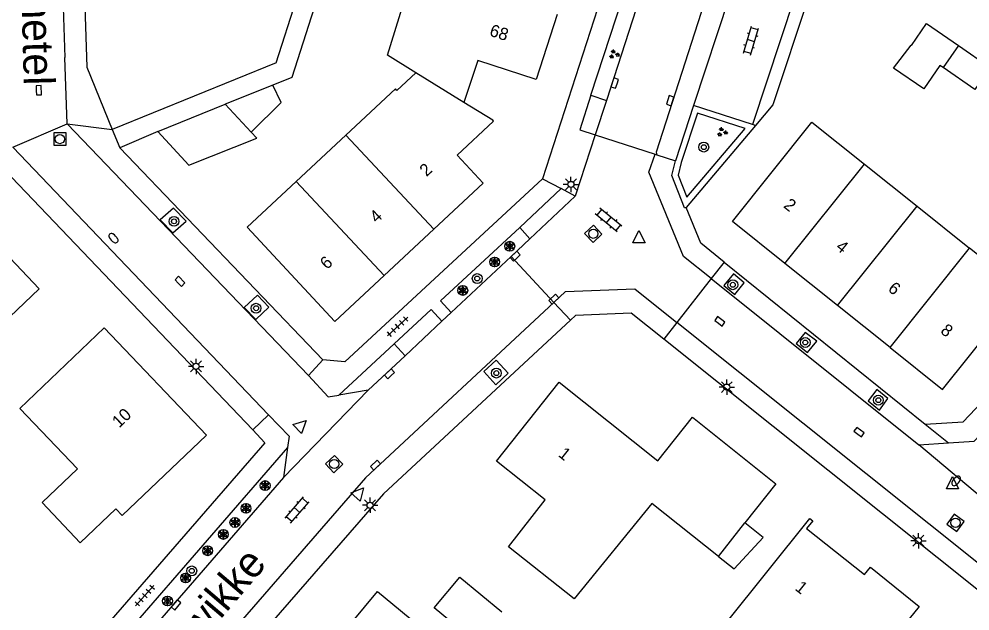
# Model space of a CAD drawing. Extents: x 136000 to 141014, y 402000 to 403500.
# Drawn here: x 137119.1 to 137196.5, y 402087.3 to 402135.5 of the extents above; entities that cross this region are included whole.
import ezdxf

# ---------------------------------------------------------------- set-up
doc = ezdxf.new("R2010")
doc.units = 0
for name, color, linetype in [('gg-afsc-erfafscheiding', 7, 'Continuous'), ('gg-anno-huisnummerreeks BGT', 7, 'Continuous'), ('gg-anno-openbare ruimte label', 7, 'Continuous'), ('gg-bbg-bijgebouw', 7, 'Continuous'), ('gg-bbg-gedigitaliseerde bebouwing', 7, 'Continuous'), ('gg-bbg-gedigitaliseerde bijgebouw', 7, 'Continuous'), ('gg-bbg-hoofdgebouw', 7, 'Continuous'), ('gg-bbg-tussenscheiding', 7, 'Continuous'), ('gg-knt-verharding', 7, 'Continuous'), ('gg-knt-verharding nz', 7, 'Continuous'), ('gt-grn-groengrens', 7, 'Continuous'), ('gt-grn-weggrens', 7, 'Continuous'), ('gt-symb-boom', 7, 'Continuous'), ('gt-symb-brandkraan', 7, 'Continuous'), ('gt-symb-groenvak', 7, 'Continuous'), ('gt-symb-klinker verharding', 7, 'Continuous'), ('gt-symb-kolk', 7, 'Continuous'), ('gt-symb-lichtmast', 7, 'Continuous'), ('gt-symb-rioolschacht', 7, 'Continuous'), ('gt-symb-solitaire heester', 7, 'Continuous'), ('gt-symb-tegel verharding', 7, 'Continuous'), ('gt-symb-waterafsluiter', 7, 'Continuous')]:
    doc.layers.add(name, color=color, linetype=linetype)

# ---------------------------------------------------------------- blocks, each defined once
blk = doc.blocks.new('gt0-KL1')
at = {"layer": 'gt-symb-klinker verharding'}
for p, q in [((-1.15, 0.3), (1.15, 0.3)), ((-1, -0.3), (-1, 0.3)), ((-0.5, 0.3), (-0.5, 0.45)), ((0, -0.3), (0, 0.3)), ((0.5, 0.3), (0.5, 0.45)), ((1, -0.3), (1, 0.3)), ((-1.15, -0.3), (1.15, -0.3)), ((-0.5, -0.45), (-0.5, -0.3)), ((0.5, -0.45), (0.5, -0.3))]:
    blk.add_line(p, q, dxfattribs=at)
blk = doc.blocks.new('gt0-BOOM')
at = {"layer": 'gt-symb-boom'}
for radius in [0.4, 0.2]:
    blk.add_circle((0, 0), radius, dxfattribs=at)
blk = doc.blocks.new('gt0-GRVAK')
at = {"layer": 'gt-symb-groenvak'}
for p, q in [((-0.11, 0.189), (-0.228, 0.24)), ((-0.182, 0.153), (0.088, 0.153)), ((-0.091, 0.211), (-0.156, 0.322)), ((-0.047, 0.214), (-0.047, 0.393)), ((-0.004, 0.211), (0.061, 0.322)), ((0.015, 0.189), (0.133, 0.24)), ((0.262, -0.052), (0.197, 0.059)), ((0.305, -0.049), (0.305, 0.13)), ((0.349, -0.052), (0.414, 0.059)), ((-0.245, -0.228), (-0.363, -0.177)), ((-0.318, -0.264), (-0.047, -0.264)), ((-0.226, -0.206), (-0.291, -0.095)), ((-0.183, -0.203), (-0.183, -0.024)), ((-0.139, -0.206), (-0.074, -0.095)), ((-0.12, -0.228), (-0.002, -0.177)), ((0.243, -0.074), (0.125, -0.023)), ((0.17, -0.11), (0.441, -0.11)), ((0.368, -0.074), (0.486, -0.023))]:
    blk.add_line(p, q, dxfattribs=at)
blk = doc.blocks.new('gt0-LMAST')
at = {"layer": 'gt-symb-lichtmast'}
for p, q in [((-0.182, 0.173), (-0.447, 0.438)), ((-0.005, 0.246), (-0.005, 0.621)), ((0.172, 0.173), (0.437, 0.438)), ((-0.255, -0.004), (-0.63, -0.004)), ((-0.182, -0.181), (-0.447, -0.446)), ((-0.005, -0.254), (-0.005, -0.629)), ((0.437, -0.446), (0.172, -0.181)), ((0.245, -0.004), (0.62, -0.004))]:
    blk.add_line(p, q, dxfattribs=at)
blk.add_circle((-0.005, -0.004), 0.25, dxfattribs=at)
blk = doc.blocks.new('gt0-KOLK')
at = {"layer": 'gt-symb-kolk'}
blk.add_lwpolyline([(0, 0), (0.375, 0), (0.375, 0.4), (-0.375, 0.4), (-0.375, 0), (0, 0)], dxfattribs=at)
blk = doc.blocks.new('gt0-WAFSL')
at = {"layer": 'gt-symb-waterafsluiter'}
for p, q in [((-0.5, -0.333), (0, 0.667)), ((0, 0.667), (0.5, -0.333)), ((0.5, -0.333), (-0.5, -0.333))]:
    blk.add_line(p, q, dxfattribs=at)
blk = doc.blocks.new('gt0-SH')
at = {"layer": 'gt-symb-solitaire heester'}
blk.add_circle((0, 0), 0.4, dxfattribs=at)
for centre, start, end in [((-0.346, 0.2), 270, 30), ((-0.346, -0.2), 330, 90), ((0, 0.4), 210, 330), ((0.346, 0.2), 150, 270), ((0.346, -0.2), 90, 210), ((0, -0.4), 30, 150)]:
    blk.add_arc(centre, 0.4, start, end, dxfattribs=at)
blk = doc.blocks.new('gt0-RS')
at = {"layer": 'gt-symb-rioolschacht'}
blk.add_lwpolyline([(-0.5, -0.5), (0.5, -0.5), (0.5, 0.5), (-0.5, 0.5)], close=True, dxfattribs=at)
blk.add_circle((0, 0), 0.375, dxfattribs=at)
blk = doc.blocks.new('gt0-BR')
at = {"layer": 'gt-symb-brandkraan'}
for centre, radius, start, end in [((-0.244, 0), 0.206, 107.56694, 252.43307), ((0.599, -2.664), 3, 106.89205, 107.56694), ((0, -0.691), 0.938, 73.10799, 106.89205), ((-0.599, -2.664), 3, 72.43309, 73.10799), ((0.244, 0), 0.206, 287.56695, 72.43309), ((0.599, 2.664), 3, 252.43307, 253.10797), ((0, 0.691), 0.938, 253.10797, 286.89206), ((-0.599, 2.664), 3, 286.89206, 287.56695)]:
    blk.add_arc(centre, radius, start, end, dxfattribs=at)
blk = doc.blocks.new('gt0-TEG1')
at = {"layer": 'gt-symb-tegel verharding'}
for p, q in [((-1.125, 0), (1.125, 0)), ((-0.9, -0.25), (-0.9, 0.25)), ((-0.45, -0.25), (-0.45, 0.25)), ((0, -0.25), (0, 0.25)), ((0.45, -0.25), (0.45, 0.25)), ((0.9, -0.25), (0.9, 0.25))]:
    blk.add_line(p, q, dxfattribs=at)

msp = doc.modelspace()

# ---------------------------------------------------------------- linework, layer by layer
at = {"layer": 'gg-afsc-erfafscheiding'}
msp.add_line((137183.617, 402138.19), (137180.426, 402128.543), dxfattribs=at)
for points in [[(137140.001, 402131.961), (137143.297, 402142.301), (137144.833, 402141.801)], [(137143.781, 402138.578), (137141.262, 402130.772), (137139.725, 402130.152)]]:
    msp.add_lwpolyline(points, dxfattribs=at)
at = {"layer": 'gg-bbg-bijgebouw'}
for p, q in [((137130.359, 402126.36), (137135.848, 402128.589)), ((137132.9, 402123.618), (137130.359, 402126.36))]:
    msp.add_line(p, q, dxfattribs=at)
for points in [[(137192.703, 402129.847), (137190.234, 402131.527), (137191.686, 402133.401), (137191.71, 402133.384), (137192.936, 402135.173)], [(137156.296, 402084.73), (137152.869, 402087.578), (137154.953, 402090.085), (137158.358, 402087.254)]]:
    msp.add_lwpolyline(points, dxfattribs=at)
at = {"layer": 'gg-bbg-gedigitaliseerde bebouwing'}
msp.add_line((137149.821, 402129.715), (137151.361, 402131.152), dxfattribs=at)
msp.add_lwpolyline([(137151.361, 402131.152), (137149.056, 402132.582), (137150.359, 402136.79), (137151.32, 402136.492)], dxfattribs=at)
at = {"layer": 'gg-bbg-gedigitaliseerde bijgebouw'}
for p, q in [((137192.936, 402135.173), (137195.516, 402133.379)), ((137139.725, 402130.152), (137135.848, 402128.589)), ((137138.427, 402125.829), (137137.964, 402126.325)), ((137132.9, 402123.618), (137138.427, 402125.829))]:
    msp.add_line(p, q, dxfattribs=at)
for points in [[(137195.516, 402133.379), (137198.101, 402131.593), (137196.858, 402129.791), (137194.272, 402131.577)], [(137194.272, 402131.577), (137194.019, 402131.752), (137192.703, 402129.847)], [(137137.964, 402126.325), (137140.407, 402128.74), (137139.725, 402130.152)], [(137176, 402091.78), (137177.268, 402090.774), (137179.629, 402093.327), (137178.152, 402094.499)]]:
    msp.add_lwpolyline(points, dxfattribs=at)
at = {"layer": 'gg-bbg-hoofdgebouw'}
for p, q in [((137141.632, 402122.307), (137145.661, 402126.067)), ((137187.877, 402123.71), (137192.153, 402120.29)), ((137152.82, 402118.408), (137156.858, 402122.176)), ((137192.153, 402120.29), (137196.428, 402116.871)), ((137152.82, 402118.408), (137148.793, 402114.648)), ((137185.678, 402112.194), (137181.402, 402115.613)), ((137189.953, 402108.774), (137185.678, 402112.194)), ((137180.67, 402097.68), (137178.152, 402094.499))]:
    msp.add_line(p, q, dxfattribs=at)
for points in [[(137162.864, 402135.881), (137161.151, 402130.6), (137156.401, 402132.148), (137155.262, 402128.731)], [(137149.821, 402129.715), (137149.704, 402129.841), (137145.661, 402126.067)], [(137156.858, 402122.176), (137154.723, 402124.439), (137157.698, 402127.211), (137157.641, 402127.285), (137155.262, 402128.731)], [(137181.402, 402115.613), (137177.127, 402119.033), (137183.602, 402127.129), (137187.877, 402123.71)], [(137120.71, 402113.567), (137114.495, 402120.096), (137112.169, 402117.924), (137110.7, 402119.498), (137110.58, 402122.986), (137101.46, 402122.685), (137101.524, 402120.656), (137102.597, 402119.529), (137099.547, 402116.614), (137104.172, 402111.774), (137107.2, 402114.668), (137111.078, 402110.611), (137106.296, 402106.041), (137109.412, 402102.781), (137120.71, 402113.567)], [(137148.793, 402114.648), (137144.786, 402110.909), (137137.632, 402118.574), (137141.632, 402122.307)], [(137189.953, 402108.774), (137194.228, 402105.355), (137200.704, 402113.451), (137196.428, 402116.871)], [(137123.839, 402098.897), (137120.955, 402096.158), (137124.06, 402092.887), (137126.945, 402095.639), (137127.468, 402095.101), (137134.33, 402101.659), (137126.015, 402110.376), (137119.143, 402103.816), (137123.839, 402098.897)], [(137176, 402091.78), (137170.57, 402096.09), (137164.26, 402088.32), (137158.9, 402092.57), (137161.89, 402096.39), (137157.92, 402099.53), (137163.03, 402105.96), (137171.06, 402099.56), (137173.88, 402103.1), (137180.67, 402097.68)], [(137192.338, 402087.711), (137189.19, 402083.82), (137191.528, 402081.943), (137187.777, 402077.273), (137176.53, 402086.27), (137183.426, 402094.866), (137183.663, 402094.68), (137183.16, 402094.05), (137187.871, 402090.297), (137188.375, 402090.91), (137192.338, 402087.711)], [(137148.25, 402088.92), (137155.43, 402082.98), (137151.91, 402078.72), (137153.68, 402077.25), (137151.51, 402074.62), (137149.696, 402076.118), (137147.74, 402073.75), (137140.58, 402079.67), (137148.25, 402088.92)]]:
    msp.add_lwpolyline(points, dxfattribs=at)
at = {"layer": 'gg-bbg-tussenscheiding'}
for p, q in [((137195.516, 402133.379), (137194.272, 402131.577)), ((137155.262, 402128.731), (137151.361, 402131.152)), ((137137.964, 402126.325), (137135.848, 402128.589)), ((137152.82, 402118.408), (137145.661, 402126.067)), ((137181.402, 402115.613), (137187.877, 402123.71)), ((137141.632, 402122.307), (137148.793, 402114.648)), ((137185.678, 402112.194), (137192.153, 402120.29)), ((137189.953, 402108.774), (137196.428, 402116.871)), ((137176, 402091.78), (137178.152, 402094.499))]:
    msp.add_line(p, q, dxfattribs=at)
at = {"layer": 'gg-knt-verharding'}
for p, q in [((137176.678, 402168.885), (137161.685, 402122.523)), ((137177.796, 402140.087), (137173.975, 402128.491)), ((137182.597, 402138.528), (137178.775, 402126.937)), ((137165.616, 402129.323), (137168.589, 402138.484)), ((137169.857, 402138.073), (137166.879, 402128.906)), ((137140.001, 402131.961), (137126.651, 402126.523)), ((137165.616, 402129.323), (137164.708, 402126.497)), ((137165.616, 402129.323), (137166.879, 402128.906)), ((137173.975, 402128.491), (137172.489, 402123.983)), ((137178.775, 402126.937), (137173.975, 402128.491)), ((137180.426, 402128.543), (137179.005, 402126.863)), ((137130.359, 402126.36), (137127.271, 402125.049)), ((137164.708, 402126.497), (137165.964, 402126.091)), ((137179.005, 402126.863), (137173.365, 402120.191)), ((137165.964, 402126.091), (137170.855, 402124.511)), ((137127.271, 402125.049), (137143.793, 402107.79)), ((137138.099, 402102.093), (137116.834, 402124.346)), ((137170.855, 402124.511), (137170.972, 402124.473)), ((137170.972, 402124.473), (137172.489, 402123.983)), ((137163.181, 402121.742), (137159.82, 402118.553)), ((137159.82, 402118.553), (137153.379, 402112.588)), ((137160.656, 402117.639), (137159.82, 402118.553)), ((137160.656, 402117.639), (137159.118, 402116.197)), ((137159.118, 402116.197), (137154.244, 402111.628)), ((137162.607, 402112.461), (137159.118, 402116.197)), ((137176.457, 402115.743), (137175.398, 402114.392)), ((137176.457, 402115.743), (137192.821, 402102.537)), ((137175.398, 402114.392), (137172.601, 402110.823)), ((137154.244, 402111.628), (137153.379, 402112.588)), ((137163.957, 402111.015), (137162.607, 402112.461)), ((137149.605, 402109.093), (137152.604, 402111.87)), ((137152.604, 402111.87), (137153.483, 402110.915)), ((137154.244, 402111.628), (137153.483, 402110.915)), ((137150.49, 402108.11), (137153.483, 402110.915)), ((137172.601, 402110.823), (137171.536, 402109.464)), ((137236.54, 402057.51), (137171.536, 402109.464)), ((137145.094, 402104.916), (137149.605, 402109.093)), ((137143.793, 402107.79), (137142.632, 402106.495)), ((137147.497, 402105.305), (137150.49, 402108.11)), ((137147.497, 402105.305), (137145.094, 402104.916)), ((137139.381, 402103.29), (137138.099, 402102.093)), ((137140.928, 402100.63), (137118.098, 402074.332)), ((137140.928, 402100.63), (137140.592, 402098.212)), ((137140.592, 402098.212), (137119.109, 402073.428))]:
    msp.add_line(p, q, dxfattribs=at)
for points in [[(137124.321, 402139.859), (137124.598, 402131.602), (137126.651, 402126.523)], [(137173.365, 402120.191), (137173.327, 402120.146), (137173.223, 402120.164), (137172.209, 402122.791), (137172.489, 402123.983)], [(137161.685, 402122.523), (137145.584, 402107.614), (137143.793, 402107.79)], [(137130.561, 402119.191), (137131.583, 402118.116), (137132.677, 402119.06), (137131.655, 402120.135), (137130.561, 402119.191)], [(137176.457, 402115.743), (137174.564, 402117.27), (137173.365, 402120.191)], [(137192.821, 402102.537), (137195.916, 402102.727), (137211.303, 402118.969)], [(137176.424, 402113.84), (137177.318, 402113.112), (137178.098, 402114.049), (137177.204, 402114.778), (137176.424, 402113.84)], [(137137.409, 402112.051), (137138.346, 402111.061), (137139.407, 402112.057), (137138.47, 402113.046), (137137.409, 402112.051)], [(137171.536, 402109.464), (137168.9, 402111.57), (137164.36, 402111.39), (137163.957, 402111.015)], [(137163.957, 402111.015), (137148.74, 402096.88), (137133.37, 402079.22)], [(137182.314, 402109.102), (137183.25, 402108.383), (137183.995, 402109.293), (137183.059, 402110.012), (137182.314, 402109.102)], [(137156.909, 402106.821), (137157.911, 402107.763), (137158.871, 402106.69), (137157.87, 402105.748), (137156.909, 402106.821)], [(137142.632, 402106.495), (137144.24, 402104.778), (137145.094, 402104.916)], [(137188.18, 402104.441), (137189.09, 402103.695), (137189.785, 402104.626), (137188.875, 402105.372), (137188.18, 402104.441)], [(137139.381, 402103.29), (137141.058, 402101.567), (137140.928, 402100.63)], [(137138.099, 402102.093), (137139.086, 402101.035), (137119.598, 402078.571)]]:
    msp.add_lwpolyline(points, dxfattribs=at)
at = {"layer": 'gg-knt-verharding nz'}
for p, q in [((137120.879, 402190.964), (137122.81, 402132.398)), ((137122.981, 402126.982), (137122.81, 402132.398)), ((137166.879, 402128.906), (137165.964, 402126.091)), ((137142.632, 402106.495), (137122.981, 402126.982)), ((137165.964, 402126.091), (137164.341, 402121.094)), ((137139.381, 402103.29), (137118.557, 402125.097)), ((137160.656, 402117.639), (137164.341, 402121.094)), ((137175.398, 402114.392), (137192.304, 402100.86)), ((137236.866, 402059.445), (137172.601, 402110.823)), ((137192.304, 402100.86), (137194.723, 402101.013))]:
    msp.add_line(p, q, dxfattribs=at)
for points in [[(137184.223, 402165.979), (137170.917, 402124.684), (137170.972, 402124.473)], [(137194.723, 402101.013), (137196.811, 402101.146), (137235.083, 402141.566)], [(137175.398, 402114.392), (137173.139, 402116.201), (137170.337, 402123.065), (137170.855, 402124.511)], [(137162.607, 402112.461), (137163.55, 402113.34), (137169.19, 402113.55), (137172.601, 402110.823)], [(137162.607, 402112.461), (137147.28, 402098.18), (137131.54, 402080.04)]]:
    msp.add_lwpolyline(points, dxfattribs=at)
at = {"layer": 'gt-grn-groengrens'}
for p, q in [((137179.005, 402126.863), (137178.775, 402126.937)), ((137149.605, 402109.093), (137150.49, 402108.11))]:
    msp.add_line(p, q, dxfattribs=at)
msp.add_lwpolyline([(137172.964, 402123.849), (137172.724, 402122.826), (137173.421, 402121.02), (137178.154, 402126.62), (137174.29, 402127.871), (137172.964, 402123.849)], dxfattribs=at)
at = {"layer": 'gt-grn-weggrens'}
for p, q in [((137118.557, 402125.097), (137122.981, 402126.982)), ((137122.981, 402126.982), (137126.651, 402126.523)), ((137126.651, 402126.523), (137127.271, 402125.049)), ((137161.685, 402122.523), (137163.181, 402121.742)), ((137164.341, 402121.094), (137163.181, 402121.742)), ((137147.497, 402105.305), (137140.592, 402098.212)), ((137192.821, 402102.537), (137194.723, 402101.013)), ((137200.33, 402094.097), (137192.304, 402100.86))]:
    msp.add_line(p, q, dxfattribs=at)

# ---------------------------------------------------------------- block references
at = {"layer": 'gt-symb-boom'}
for p in [(137174.8, 402125.096), (137131.691, 402119.051), (137156.362, 402114.399), (137177.161, 402113.89), (137138.365, 402111.983), (137183.057, 402109.192), (137157.922, 402106.7), (137189.007, 402104.496), (137133.133, 402090.6)]:
    msp.add_blockref('gt0-BOOM', p, dxfattribs=at)
at = {"layer": 'gt-symb-brandkraan'}
for p, rotation in [((137126.759, 402117.688), -46.29643001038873), ((137195.338, 402097.926), 49.541618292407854)]:
    msp.add_blockref('gt0-BR', p, dxfattribs=dict(at, rotation=rotation))
at = {"layer": 'gt-symb-groenvak'}
for p in [(137167.488, 402132.652), (137176.289, 402126.321)]:
    msp.add_blockref('gt0-GRVAK', p, dxfattribs=at)
at = {"layer": 'gt-symb-klinker verharding'}
for p, rotation in [((137178.643, 402133.762), 73.19645198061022), ((137167.055, 402119.163), 141.00900595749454), ((137141.704, 402095.56), 49.05673786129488)]:
    msp.add_blockref('gt0-KL1', p, dxfattribs=dict(at, rotation=rotation))
at = {"layer": 'gt-symb-kolk'}
for p, rotation in [((137120.482, 402129.719), -88.22439947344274), ((137167.741, 402130.251), 71.94544753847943), ((137172.253, 402128.821), 71.94544753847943), ((137159.576, 402116.069), 43.13672087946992), ((137132.03, 402114.031), -46.215428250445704), ((137162.726, 402112.58), 43.13672087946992), ((137175.985, 402110.756), -36.66359247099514), ((137149.351, 402106.494), 43.13672087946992), ((137187.322, 402101.74), -36.66359246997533), ((137148.23, 402099.062), 43.13672087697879), ((137132.007, 402087.701), 50.15042857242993)]:
    msp.add_blockref('gt0-KOLK', p, dxfattribs=dict(at, rotation=rotation))
at = {"layer": 'gt-symb-lichtmast'}
for p in [(137163.99, 402122.066), (137133.487, 402107.25), (137176.674, 402105.56), (137147.647, 402095.942), (137192.267, 402093.061)]:
    msp.add_blockref('gt0-LMAST', p, dxfattribs=at)
at = {"layer": 'gt-symb-rioolschacht'}
msp.add_blockref('gt0-RS', (137122.397, 402125.752), dxfattribs=at)
for p, rotation in [((137165.807, 402118.045), 43.13672087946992), ((137144.725, 402099.298), 43.136720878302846), ((137195.283, 402094.515), -36.66359246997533)]:
    msp.add_blockref('gt0-RS', p, dxfattribs=dict(at, rotation=rotation))
at = {"layer": 'gt-symb-solitaire heester'}
for p in [(137159.009, 402117.028), (137157.776, 402115.746), (137155.187, 402113.431), (137139.103, 402097.545), (137137.546, 402095.689), (137136.641, 402094.538), (137135.704, 402093.563), (137134.429, 402092.237), (137132.631, 402090.026), (137131.156, 402088.147)]:
    msp.add_blockref('gt0-SH', p, dxfattribs=at)
at = {"layer": 'gt-symb-tegel verharding'}
for p, rotation in [((137149.879, 402110.488), 42.770928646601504), ((137129.305, 402088.577), 48.00000872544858)]:
    msp.add_blockref('gt0-TEG1', p, dxfattribs=dict(at, rotation=rotation))
at = {"layer": 'gt-symb-waterafsluiter'}
for p in [(137169.522, 402117.651), (137195.037, 402097.624)]:
    msp.add_blockref('gt0-WAFSL', p, dxfattribs=at)
for p, rotation in [((137141.949, 402102.371), -46.29643001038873), ((137146.67, 402096.863), -41.067356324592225)]:
    msp.add_blockref('gt0-WAFSL', p, dxfattribs=dict(at, rotation=rotation))

# ---------------------------------------------------------------- texts
at = {"layer": 'gg-anno-huisnummerreeks BGT'}
for s, rotation, p in [('68', 342, (137157.292, 402134.187)), ('2', 43, (137152.234, 402122.648)), ('2', 321.3, (137181.22, 402120.242)), ('4', 43, (137148.177, 402118.861)), ('4', 321.4, (137185.468, 402116.842)), ('6', 43, (137144.135, 402115.088)), ('6', 321.3, (137189.717, 402113.446)), ('8', 321.3, (137193.991, 402110.027)), ('10', 43.6, (137127.223, 402102.187)), ('1', 321.5, (137162.889, 402099.977)), ('1', 321.5, (137182.159, 402089.094))]:
    msp.add_text(s, height=1, rotation=rotation, dxfattribs=at).set_placement(p)
at = {"layer": 'gg-anno-openbare ruimte label'}
for s, rotation, p in [('Dovenetel', 271.5, (137119.071, 402145.151)), ('Vogelwikke', 49.5, (137128.339, 402078.271))]:
    msp.add_text(s, height=2.5, rotation=rotation, dxfattribs=at).set_placement(p)

doc.saveas('drawing.dxf')
